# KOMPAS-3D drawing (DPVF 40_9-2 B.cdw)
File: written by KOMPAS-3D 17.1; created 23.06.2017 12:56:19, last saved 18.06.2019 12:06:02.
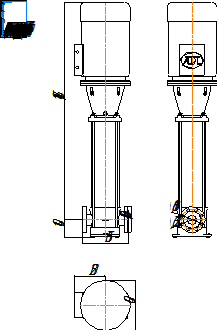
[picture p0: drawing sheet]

Sheet 1: A4, portrait

Title block, sheet 1: name: DPVF 40_9-2 B; material: Внимание! Данный продукт является объектом авторского права ООО «Торговый Дом АДЛ». / Запрещается изменение, копирование, распространение / (в том числе путем копирования на другие сайты и ресурсы в Интернете) / или любое иное использование информации и объектов без предварительного / согласия правообладателя (ООО «Торговый Дом АДЛ»).; scale: 1:1; sheets: 1; organisation: ООО "Торговый дом АДЛ"; sheet format: A4; stored path: C:\Клочков АВ\Насосы\DP PAMS\DPVF 40\Компас 2d\DPVF 40_9-2 B.cdw

Views: Спереди 1
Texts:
  Клочков АВ
  ООО АДЛ ГРУПП
Dimensions and other numbers on the sheet: 365; 250; 400; 209,6; 1741,5; 140; 168,1; 76,2; 1:1; 1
